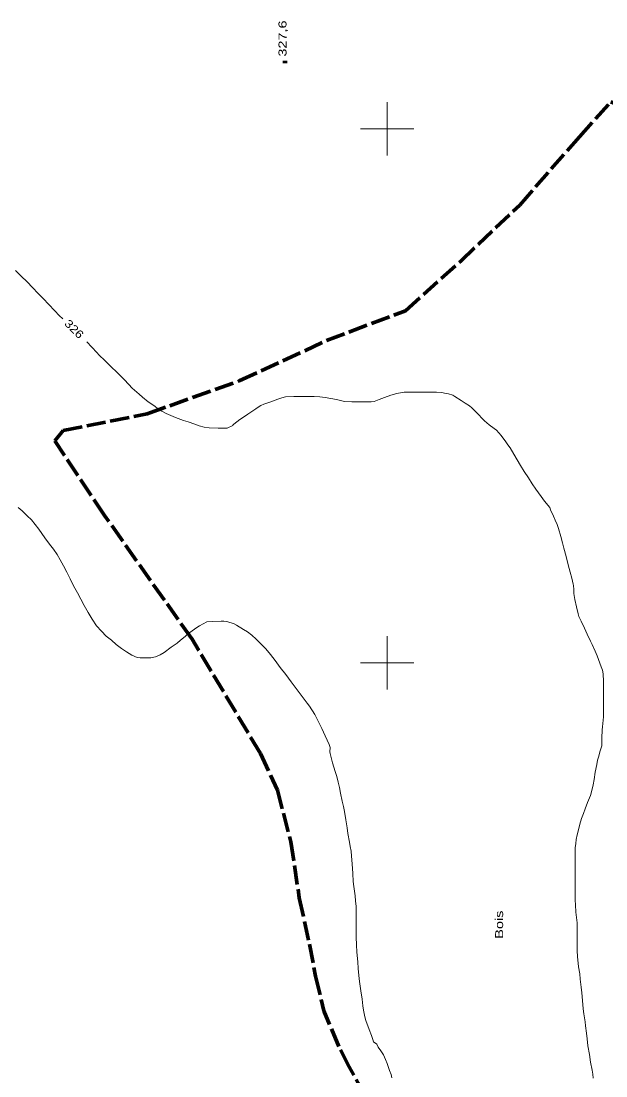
# Model space of a CAD drawing. Extents: x 240591 to 242335, y 5323482 to 5326937.
# Drawn here: x 240862.8 to 241082, y 5325645.2 to 5326040.4 of the extents above; entities that cross this region are included whole.
import ezdxf

# ---------------------------------------------------------------- set-up
doc = ezdxf.new("R2010")
doc.units = 0
doc.header["$LTSCALE"] = 1.2
doc.linetypes.add('LONG_DASHED', pattern=[7.5, 6, -1.5])
for name, color, linetype, lineweight in [('2', 7, 'Continuous', 13), ('22', 7, 'LONG_DASHED', 70), ('3', 7, 'Continuous', 140), ('44', 7, 'Continuous', 25), ('61', 7, 'Continuous', 13)]:
    doc.layers.add(name, color=color, linetype=linetype, lineweight=lineweight)

msp = doc.modelspace()

# ---------------------------------------------------------------- linework, layer by layer
at = {"layer": '2', "linetype": 'LONG_DASHED'}
for points in [[(240878.5, 5325928.8), (240877.1, 5325930.1), (240875.4, 5325931.9), (240873.1, 5325934.3), (240871.2, 5325936.4), (240869.2, 5325938.4), (240867.1, 5325940.6), (240865.1, 5325942.7), (240862.9, 5325944.9), (240860.7, 5325947)], [(240942.2, 5325888.9), (240940.1, 5325887.9), (240939.3, 5325887.9), (240936.7, 5325887.9), (240933.3, 5325888), (240931.4, 5325888.3), (240929.6, 5325888.8), (240927.9, 5325889.4), (240925.5, 5325890.3), (240923.7, 5325890.8), (240920.7, 5325891.9), (240918.9, 5325892.6), (240917.2, 5325893.4), (240915.6, 5325894.3), (240914.1, 5325895.2), (240912.9, 5325896.1), (240910.5, 5325897.8), (240908.3, 5325899.5), (240907.1, 5325900.6), (240904.5, 5325902.9), (240903.2, 5325904.3), (240901.4, 5325906.1), (240900, 5325907.6), (240898.4, 5325909.1), (240896.8, 5325910.6), (240894.2, 5325913.2), (240892.1, 5325915.2), (240891.2, 5325916.3), (240889.3, 5325918.3), (240887.5, 5325920.2)], [(241061, 5325858.2), (241059, 5325860.6), (241057.7, 5325862.3), (241055.7, 5325865.1), (241054.4, 5325867), (241053, 5325869.3), (241051.4, 5325871.6), (241050, 5325873.9), (241048.7, 5325876), (241047.5, 5325878.2), (241046.1, 5325880.5), (241045.3, 5325881.6), (241044.5, 5325882.8), (241042.7, 5325885.1), (241041, 5325887.1), (241040.1, 5325887.8), (241038.3, 5325889.2), (241036.5, 5325890.6), (241035.8, 5325891.4), (241034.2, 5325893.1), (241031.8, 5325895.5), (241030.9, 5325896.2), (241029.3, 5325897.2), (241027.8, 5325898.3), (241025.4, 5325899.8), (241024.6, 5325900.2), (241023, 5325900.7), (241022.1, 5325900.9), (241020.4, 5325901.2), (241018.5, 5325901.4), (241017.5, 5325901.4), (241014.7, 5325901.4), (241012.1, 5325901.4), (241009.6, 5325901.4), (241006.4, 5325901.4), (241005.6, 5325901.3), (241003.6, 5325900.9), (241001.4, 5325900.2), (240999, 5325899.4), (240997, 5325898.6), (240995.2, 5325897.9), (240994, 5325897.8), (240992.8, 5325897.8), (240990, 5325897.8), (240986.8, 5325897.8), (240984, 5325897.9), (240983, 5325898.1), (240981, 5325898.6), (240978.9, 5325899), (240976.8, 5325899.4), (240974.8, 5325899.6), (240972.7, 5325899.7), (240970.7, 5325899.7), (240968.2, 5325899.7), (240965, 5325899.7), (240961.9, 5325899.6), (240960.5, 5325899.3), (240959.1, 5325898.8), (240958.1, 5325898.4), (240956, 5325897.6), (240954.9, 5325897.3), (240953.8, 5325896.9), (240952.7, 5325896.4), (240951.7, 5325895.8), (240950.8, 5325895.2), (240947.8, 5325893.2), (240945.8, 5325891.8), (240944.8, 5325891.1), (240942.5, 5325889.4), (240942.2, 5325889), (240942.2, 5325888.9)], [(240978.6, 5325766.6), (240978.7, 5325768.3), (240978.3, 5325769.4), (240976.8, 5325772.6), (240975.5, 5325775.4), (240974.1, 5325778.4), (240972.9, 5325780.6), (240970.9, 5325783.7), (240970.1, 5325784.8), (240968.6, 5325786.8), (240966.3, 5325789.9), (240964.1, 5325792.8), (240962, 5325795.6), (240959.9, 5325798.2), (240958.1, 5325800.8), (240956.3, 5325803.1), (240954.6, 5325805.2), (240952.7, 5325807.1), (240950.9, 5325808.8), (240949.3, 5325810.3), (240947.7, 5325811.6), (240946.2, 5325812.5), (240943.6, 5325814.1), (240942.4, 5325814.7), (240941.1, 5325815.1), (240939.9, 5325815.4), (240938.8, 5325815.6), (240937.8, 5325815.6), (240934.7, 5325815.5), (240932.4, 5325815.3), (240931.1, 5325814.6), (240929.7, 5325813.8), (240928.3, 5325813), (240926.4, 5325811.6), (240925.5, 5325811), (240924.3, 5325809.8), (240922.6, 5325808.4), (240921.3, 5325807.4), (240919.1, 5325805.8), (240916.4, 5325803.9), (240914.9, 5325803), (240913.2, 5325802.2), (240911.5, 5325801.8), (240909.8, 5325801.8), (240907.5, 5325801.8), (240906.3, 5325802), (240904.3, 5325802.9), (240902.3, 5325804.1), (240900.4, 5325805.4), (240898.5, 5325806.8), (240896.7, 5325808.4), (240894.7, 5325810), (240892.9, 5325811.8), (240891.1, 5325813.8), (240889.5, 5325816.3), (240887.9, 5325818.8), (240886.5, 5325821.4), (240885.2, 5325823.8), (240883.9, 5325826.2), (240882.5, 5325828.8), (240881.2, 5325831.4), (240879.9, 5325833.9), (240878.7, 5325836.3), (240877.5, 5325838.5), (240876.3, 5325840.6), (240874.9, 5325842.6), (240873.5, 5325844.4), (240871.7, 5325846.8), (240869.5, 5325850), (240868.1, 5325851.8), (240866.7, 5325853.5), (240865.1, 5325855), (240863.2, 5325856.9), (240861.7, 5325858.2)], [(241079.8, 5325766.6), (241080.5, 5325768.9), (241080.5, 5325769.5), (241080.5, 5325771.8), (241080.6, 5325774.9), (241080.7, 5325776), (241081.1, 5325779.7), (241081.1, 5325781), (241081.1, 5325784.5), (241081.1, 5325787), (241081.1, 5325789.9), (241081.1, 5325793), (241081, 5325795.8), (241080.7, 5325797.2), (241080.3, 5325798.5), (241079.8, 5325799.9), (241078.8, 5325802.6), (241078, 5325804.4), (241076.9, 5325806.8), (241076.3, 5325808.1), (241075, 5325810.7), (241074, 5325813), (241072.7, 5325815.6), (241071.9, 5325817.3), (241071.6, 5325818.3), (241071, 5325821), (241070.4, 5325823.7), (241070, 5325825.9), (241070, 5325827.5), (241069.9, 5325828.9), (241069.7, 5325829.5), (241069.2, 5325831.7), (241068.6, 5325833.9), (241067.9, 5325836.7), (241067.1, 5325839.8), (241066.3, 5325842.9), (241065.7, 5325844.9), (241065.1, 5325847.3), (241064.2, 5325850.3), (241063.7, 5325851.8), (241063, 5325853.4), (241062.4, 5325854.9), (241061.2, 5325857.3), (241061, 5325858.2)], [(240996.1, 5325657.1), (240994.9, 5325658), (240994.7, 5325658.8), (240994.1, 5325660.3), (240993.3, 5325662.6), (240992, 5325666), (240991.7, 5325667.3), (240991.1, 5325669.8), (240990.9, 5325671.4), (240990.6, 5325673.9), (240990.1, 5325677.1), (240989.6, 5325680.6), (240989.4, 5325682.8), (240989.2, 5325685.5), (240989, 5325688), (240988.7, 5325691.5), (240988.5, 5325694.3), (240988.4, 5325697.2), (240988.4, 5325699.4), (240988.4, 5325702.2), (240988.4, 5325705.1), (240988.4, 5325708.7), (240988.2, 5325710.8), (240988, 5325712.7), (240987.5, 5325716.2), (240987.3, 5325718.1), (240987.1, 5325721), (240986.9, 5325724.7), (240986.7, 5325727.5), (240986.5, 5325729.4), (240986.2, 5325731.1), (240985.9, 5325732.8), (240985.3, 5325736), (240985, 5325738.2), (240984.5, 5325741.1), (240984, 5325744.3), (240983.6, 5325746.1), (240983.1, 5325748.2), (240982.5, 5325751.1), (240982.1, 5325753.2), (240981.6, 5325755.3), (240981.1, 5325757.4), (240980.5, 5325759.2), (240979.6, 5325762.5), (240979, 5325764.5), (240978.7, 5325766), (240978.6, 5325766.6)], [(241077.3, 5325644.3), (241077.1, 5325645.8), (241076.9, 5325647.3), (241076.3, 5325650.3), (241075.9, 5325653.2), (241075.3, 5325656.5), (241075, 5325659.1), (241074.7, 5325661.2), (241074.4, 5325664), (241074.2, 5325665.5), (241073.8, 5325668.4), (241073.5, 5325670.3), (241073.3, 5325673.4), (241073, 5325676.3), (241072.7, 5325678.5), (241072.4, 5325681.4), (241072.2, 5325683.5), (241071.8, 5325686.1), (241071.4, 5325690), (241071.3, 5325692.1), (241071.2, 5325694.2), (241071.2, 5325696.1), (241071.2, 5325699.5), (241071.2, 5325702.6), (241071, 5325704.5), (241070.8, 5325706.6), (241070.6, 5325709.3), (241070.5, 5325711.1), (241070.5, 5325712.8), (241070.5, 5325715.3), (241070.5, 5325718.1), (241070.5, 5325721.6), (241070.5, 5325724.3), (241070.5, 5325727.4), (241070.5, 5325730.7), (241070.7, 5325732.3), (241070.9, 5325733.8), (241071.3, 5325735.5), (241071.7, 5325737.4), (241072.3, 5325739.5), (241072.9, 5325741.6), (241073.6, 5325743.5), (241074.2, 5325745.3), (241075.1, 5325747.6), (241076.2, 5325750.3), (241076.8, 5325752.1), (241077.2, 5325754.2), (241077.6, 5325756.3), (241078, 5325759), (241078.6, 5325761.9), (241078.9, 5325763.5), (241079.4, 5325765), (241079.8, 5325766.6)], [(241001.8, 5325644.5), (241001.5, 5325645.7), (241000.9, 5325647.2), (241000, 5325649.8), (240999.4, 5325651.4), (240998.7, 5325653.1), (240997.7, 5325654.6), (240996.7, 5325656), (240996.1, 5325657.1)]]:
    msp.add_lwpolyline(points, dxfattribs=at)
at = {"layer": '22'}
for points in [[(240878.6, 5325887), (240910.1, 5325893.3), (240944.6, 5325905.6), (240977.3, 5325920.7), (241006.9, 5325931.9), (241027.6, 5325950.5), (241049.7, 5325971.5), (241072.1, 5325997.1), (241083.9, 5326010.2), (241099.8, 5326003.5), (241127.5, 5325990.3), (241153.7, 5325975), (241180.6, 5325956.3), (241199.3, 5325939.6), (241221, 5325919.5), (241234.5, 5325909.4), (241253.5, 5325900.9), (241283.5, 5325886.4), (241311.3, 5325874.6), (241329.3, 5325867.7), (241351.2, 5325858.8), (241373.9, 5325850)], [(240952.5, 5325766), (240926.9, 5325808.8), (240894.1, 5325855.2), (240875.4, 5325883.2), (240878.6, 5325887)], [(240952.5, 5325766), (240958.9, 5325752.3), (240963.9, 5325732.9), (240967.1, 5325711.9), (240970.9, 5325694.6), (240973.2, 5325682.6), (240976.3, 5325669.6)], [(241048.3, 5325461.2), (241048.3, 5325461.2), (241050.1, 5325466.7), (241050.7, 5325473.8), (241047.7, 5325482.2), (241045.7, 5325494.8), (241044.2, 5325511.9), (241042.5, 5325533.1), (241038.7, 5325547.3), (241031.2, 5325562.3), (241024.5, 5325574), (241017.9, 5325586.3), (241011.4, 5325601.3), (241004.5, 5325614.9), (240999.3, 5325626.1), (240991.9, 5325637.6), (240985.8, 5325648.6), (240981.9, 5325656.2), (240976.3, 5325669.6)]]:
    msp.add_lwpolyline(points, dxfattribs=at)
at = {"layer": '3'}
msp.add_line((240961.8, 5326024.7), (240961.8, 5326025.5), dxfattribs=at)
at = {"layer": '61'}
for points in [[(241000, 5326010), (241000, 5326000), (241000, 5325990)], [(240990, 5326000), (241000, 5326000), (241010, 5326000)], [(241000, 5325810), (241000, 5325800), (241000, 5325790)], [(240990, 5325800), (241000, 5325800), (241010, 5325800)]]:
    msp.add_lwpolyline(points, dxfattribs=at)

# ---------------------------------------------------------------- texts
at = {"layer": '2', "width": 1.2}
msp.add_text('326', height=3, rotation=315.368, dxfattribs=at).set_placement((240878.8, 5325926.8))
at = {"layer": '3', "width": 1.35}
msp.add_text('327,6', height=3, rotation=90, dxfattribs=at).set_placement((240962.3, 5326027.1))
at = {"layer": '44', "width": 1.35}
msp.add_text('Bois', height=3, rotation=90, dxfattribs=at).set_placement((241043.5, 5325696.6))

doc.saveas('drawing.dxf')
